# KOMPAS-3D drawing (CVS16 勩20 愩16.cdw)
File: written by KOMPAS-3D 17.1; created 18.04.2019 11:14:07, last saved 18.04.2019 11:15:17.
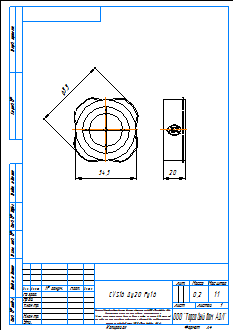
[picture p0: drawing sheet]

Sheet 1: A4, portrait

Title block, sheet 1: name: CVS16 Ду20 Ру16; material: Внимание! Данный продукт является объектом авторского права ООО «Торговый Дом АДЛ». / Запрещается изменение, копирование, распространение / (в том числе путем копирования на другие сайты и ресурсы в Интернете) / или любое иное использование информации и объектов без предварительного / согласия правообладателя (ООО «Торговый Дом АДЛ»).; mass: 0,2; sheets: 1; organisation: ООО "Торговый дом АДЛ"; sheet format: A4; stored path: \\adlc.lan\data\АДЛ_ПКД\3D-модели\ADL production\Клапаны обратные ГРАНЛОК\CVS16\KOMPAS 2D\CVS16 Ду20 Ру16.cdw

Views: Вид 1, Проекционный вид 2
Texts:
  user
Dimensions and other numbers on the sheet: 65,5; 54,5; 20; 1:1; 1; 0,2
